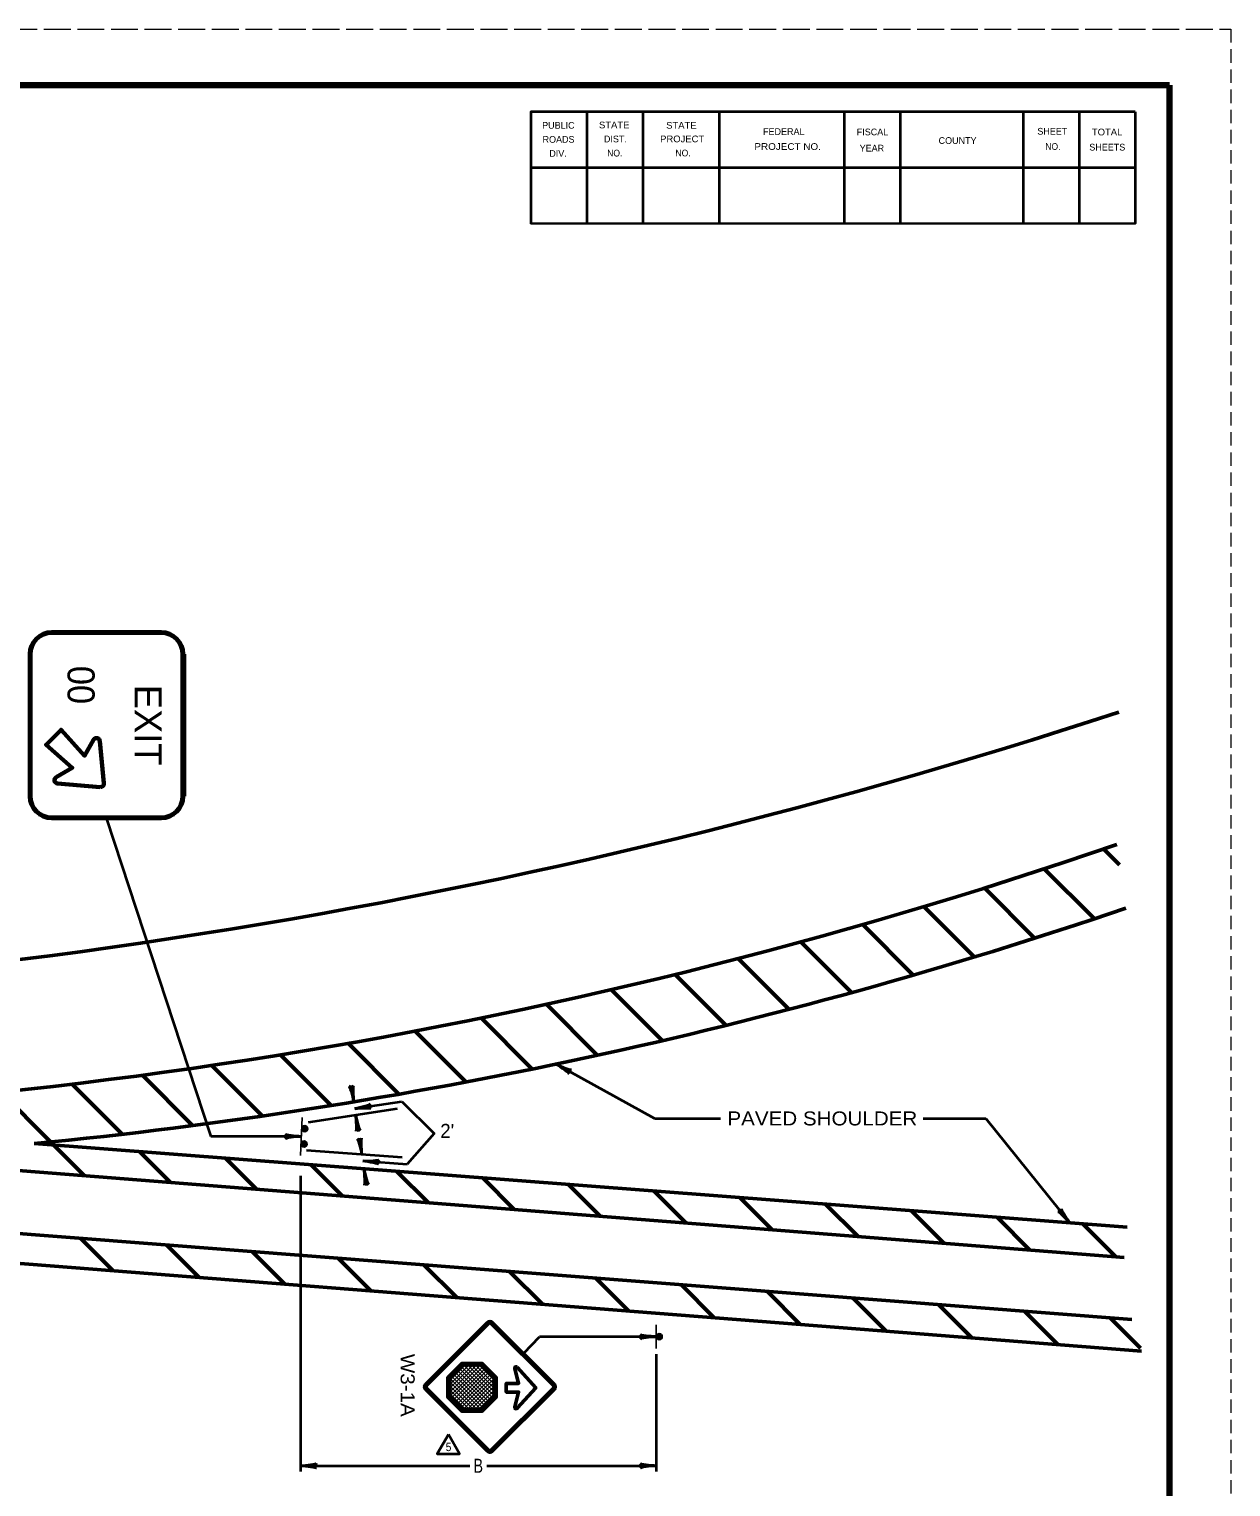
# Model space of a CAD drawing. Extents: x -281 to 399, y -258 to 182.
# Drawn here: x 184.7 to 399.4, y -78.8 to 181.6 of the extents above; entities that cross this region are included whole.
import ezdxf
from ezdxf.enums import TextEntityAlignment as Align

# ---------------------------------------------------------------- set-up
doc = ezdxf.new("R2010")
doc.units = 0
doc.header["$LTSCALE"] = 0.8
doc.linetypes.add('LONG_DASHED', pattern=[7.5, 6, -1.5])
doc.linetypes.add('MEDIUM_DASHED', pattern=[4.5, 3, -1.5])
for name, color, linetype, lineweight in [('1', 7, 'Continuous', 53), ('4', 7, 'Continuous', 25), ('61', 7, 'Continuous', 35)]:
    doc.layers.add(name, color=color, linetype=linetype, lineweight=lineweight)
doc.layers.add('2', color=7, linetype='Continuous')

msp = doc.modelspace()

# ---------------------------------------------------------------- hatches: boundary and pattern name
at = {"layer": '4'}
for points in [[(234.0025, -14.3221, 1), (233.9497, -15.4142, 1)], [(233.8666, -17.0612, 1), (233.8138, -18.1532, 1)], [(297.2901, -52.5626, 1), (297.2901, -51.4692, 1)]]:
    msp.add_hatch(color=256, dxfattribs=at).paths.add_polyline_path(points)

# ---------------------------------------------------------------- linework, layer by layer
at = {"layer": '1', "linetype": 'MEDIUM_DASHED', "lineweight": 13}
msp.add_line((399.3899, 181.553), (399.3699, -258.467), dxfattribs=at)
at = {"layer": '1', "lineweight": 13}
for p, q in [((188.816, 73.9491), (208.3032, 73.9491)), ((208.3032, 40.4701), (188.816, 40.4701)), ((255.3848, -60.5826), (266.6443, -49.3231)), ((267.4488, -49.3231), (278.7084, -60.5826)), ((266.6443, -72.6466), (255.3848, -61.3872)), ((278.7084, -61.3872), (267.4488, -72.6466))]:
    msp.add_line(p, q, dxfattribs=at)
at = {"layer": '1', "lineweight": 70}
for p, q in [((188.816, 73.7737), (208.3032, 73.7737)), ((184.9185, 44.5429), (184.9185, 69.8762)), ((212.2006, 69.8762), (212.2006, 44.5429)), ((212.3758, 69.8762), (212.3758, 44.5429)), ((208.3032, 40.6455), (188.816, 40.6455)), ((255.6529, -60.616), (266.678, -49.5908)), ((267.4151, -49.5908), (278.4406, -60.616)), ((266.678, -72.3786), (255.6529, -61.3534)), ((278.4406, -61.3534), (267.4151, -72.3786))]:
    msp.add_line(p, q, dxfattribs=at)
at = {"layer": '1', "lineweight": 60}
for p, q in [((198.0905, 46.8322), (197.3739, 54.3833)), ((189.8228, 46.8046), (197.429, 46.1709))]:
    msp.add_line(p, q, dxfattribs=at)
at = {"layer": '1', "lineweight": 35}
for p, q in [((198.5596, 40.4701), (217.1863, -16.2451)), ((296.448, -13.0323), (278.8727, -3.3218)), ((242.2686, -7.1048), (242.7253, -10.0699)), ((242.9123, -11.2834), (251.3292, -9.9868)), ((234.6656, -13.6853), (250.5111, -11.2443)), ((243.0825, -12.3887), (243.5392, -15.3537)), ((296.448, -13.0323), (308.2117, -13.0323)), ((344.4182, -13.0323), (355.6099, -13.0323)), ((355.6099, -13.0323), (370.6327, -31.6842)), ((233.3559, -16.2451), (217.1863, -16.2451)), ((243.712, -16.4758), (244.1688, -19.4409)), ((234.2569, -18.7163), (251.3497, -19.9658)), ((244.3504, -20.6193), (252.2623, -21.1977)), ((233.1867, -23.2798), (233.1867, -76.0738)), ((244.5684, -22.0352), (245.0251, -25.0001)), ((273.0787, -54.9528), (275.8959, -52.0159)), ((296.7568, -52.0159), (275.8959, -52.0159)), ((296.7568, -55.1492), (296.7568, -76.0738)), ((233.1867, -75.0738), (263.4717, -75.0738)), ((266.4717, -75.0738), (296.7568, -75.0738))]:
    msp.add_line(p, q, dxfattribs=at)
at = {"layer": '1'}
for p, q in [((379.5286, 32.2714), (376.659, 35.141)), ((374.995, 22.6629), (366.0127, 31.6452)), ((364.3436, 19.1722), (355.3664, 28.1493)), ((353.4922, 15.8814), (344.4977, 24.8759)), ((342.6407, 12.5907), (333.5824, 21.6491)), ((331.5705, 9.5187), (322.5365, 18.5528)), ((320.4375, 6.5097), (311.3434, 15.6037)), ((309.1587, 3.6464), (300.1063, 12.6988)), ((297.7339, 0.929), (288.6256, 10.0373)), ((286.2294, -1.7086), (277.1449, 7.3759)), ((262.7521, -6.5156), (253.6231, 2.6134)), ((274.5018, -4.1232), (265.4023, 4.9762)), ((250.7093, -8.6149), (241.6437, 0.4507)), ((238.6665, -10.7143), (229.5537, -1.6015)), ((226.3203, -12.5102), (217.3157, -3.5057)), ((201.294, -15.7682), (192.3803, -6.8545)), ((213.9486, -14.2806), (204.9017, -5.2338)), ((188.5777, -17.1941), (179.6273, -8.2436)), ((64.0117, -12.9926), (380.3567, -37.8742)), ((380.8884, -32.4693), (185.6334, -17.5242)), ((194.6516, -23.2678), (189.1793, -17.7957)), ((210.001, -24.4752), (204.4937, -18.9678)), ((225.3504, -25.6824), (219.808, -20.14)), ((240.6998, -26.8897), (235.1222, -21.3122)), ((256.0492, -28.097), (250.4366, -22.4843)), ((271.3987, -29.3043), (265.7509, -23.6565)), ((286.7481, -30.5116), (281.0652, -24.8287)), ((302.0975, -31.7189), (296.3795, -26.0008)), ((317.4469, -32.9262), (311.6938, -27.173)), ((332.7963, -34.1334), (327.0081, -28.3452)), ((348.1457, -35.3407), (342.3224, -29.5173)), ((363.4952, -36.548), (357.6368, -30.6896)), ((378.8447, -37.7553), (372.951, -31.8618)), ((199.7399, -40.2283), (193.9436, -34.432)), ((215.0813, -41.4277), (209.2687, -35.615)), ((230.4227, -42.6269), (224.5939, -36.7981)), ((245.7643, -43.8263), (239.919, -37.9811)), ((261.1057, -45.0256), (255.2442, -39.1641)), ((276.4471, -46.2249), (270.5693, -40.3471)), ((291.7886, -47.4242), (285.8945, -41.5301)), ((307.13, -48.6235), (301.2197, -42.7132)), ((322.4715, -49.8228), (316.5448, -43.8962)), ((337.8129, -51.0222), (331.8699, -45.0792)), ((353.1543, -52.2214), (347.1951, -46.2622)), ((368.4958, -53.4207), (362.5202, -47.4452)), ((383.2576, -54.0403), (377.8454, -48.6283)), ((271.4887, -57.6933), (272.1795, -60.3649))]:
    msp.add_line(p, q, dxfattribs=at)
at = {"layer": '1', "lineweight": 25}
for p, q in [((233.5251, -12.8492), (233.1867, -19.6409)), ((259.744, -59.9841), (262.7772, -56.9508)), ((259.744, -60.6731), (263.466, -56.9508)), ((259.744, -61.3619), (264.1548, -56.9508)), ((259.744, -62.0509), (264.844, -56.9508)), ((259.744, -62.7399), (265.5328, -56.9508)), ((267.6381, -63.0611), (261.8367, -57.2592)), ((267.9492, -62.6829), (262.2171, -56.9508)), ((267.9492, -61.9941), (262.906, -56.9508)), ((267.9492, -61.3052), (263.5952, -56.9508)), ((267.9492, -60.6159), (264.2842, -56.9508)), ((267.9492, -59.9271), (264.973, -56.9508)), ((265.5737, -65.1303), (259.7699, -59.3261)), ((260.0832, -63.0892), (265.8851, -57.2881)), ((265.9178, -64.7854), (260.1142, -58.9819)), ((260.4274, -63.4343), (266.2293, -57.6322)), ((266.262, -64.4404), (260.4585, -58.6375)), ((260.7716, -63.7792), (266.574, -57.9767)), ((266.6059, -64.0957), (260.8032, -58.2927)), ((261.1157, -64.1241), (266.9185, -58.3215)), ((266.9499, -63.7507), (261.1477, -57.9484)), ((261.4597, -64.4692), (267.2628, -58.6657)), ((267.294, -63.4059), (261.492, -57.6038)), ((261.8036, -64.814), (267.6075, -59.0104)), ((262.1506, -65.1561), (267.9492, -59.3573)), ((264.9104, -65.1561), (259.744, -59.9897)), ((264.2214, -65.1561), (259.744, -60.6786)), ((263.5324, -65.1561), (259.744, -61.3676)), ((262.8437, -65.1561), (259.744, -62.0565)), ((262.8396, -65.1561), (267.9492, -60.0466)), ((263.5287, -65.1561), (267.9492, -60.7354)), ((264.2174, -65.1561), (267.9492, -61.4244)), ((264.9065, -65.1561), (267.9492, -62.1133)), ((262.1544, -65.1561), (259.744, -62.7454))]:
    msp.add_line(p, q, dxfattribs=at)
at = {"layer": '1', "lineweight": 60}
msp.add_lwpolyline([(196.2577, 54.6175), (194.6318, 51.7514), (190.4428, 56.4089), (187.7697, 53.7357), (192.4547, 49.6017), (189.5749, 47.9346)], dxfattribs=at)
at = {"layer": '1'}
for points in [[(-241.1311, -9.5059), (-85.5166, -12.8592), (381.7234, -48.9276)], [(383.4217, -54.5876), (-6.4749, -24.1076), (-241.3148, -19.9913)], [(269.9762, -60.3649), (272.1795, -60.3649), (271.4887, -57.6933)], [(271.9108, -57.4703), (275.2274, -61.1328), (271.9108, -64.8025)], [(271.9108, -64.8025), (275.2274, -61.1328), (271.9108, -57.4703)], [(271.4887, -64.5722), (272.1795, -61.9082), (269.9762, -61.9082), (269.9762, -60.3649)], [(272.1795, -60.3649), (269.9762, -60.3649), (269.9762, -61.9082), (272.1795, -61.9082), (271.4887, -64.5722)]]:
    msp.add_lwpolyline(points, dxfattribs=at)
at = {"layer": '1', "lineweight": 35}
msp.add_lwpolyline([(251.3292, -9.9868), (257.1044, -15.7097), (252.2623, -21.1977)], dxfattribs=at)
for points in [[(259.4561, -59.2312), (262.03, -56.663), (265.6633, -56.663), (268.2369, -59.2312), (268.2369, -62.8702), (265.6633, -65.444), (262.03, -65.444), (259.4561, -62.8702)], [(259.6272, -69.4922), (257.6272, -72.9563), (261.6272, -72.9563)]]:
    msp.add_lwpolyline(points, close=True, dxfattribs=at)
at = {"layer": '1', "lineweight": 70}
msp.add_lwpolyline([(259.744, -59.3522), (262.1452, -56.9508), (265.5481, -56.9508), (267.9492, -59.3522), (267.9492, -62.7493), (265.5481, -65.1561), (262.1452, -65.1561), (259.744, -62.7493)], close=True, dxfattribs=at)
at = {"layer": '1', "lineweight": 13}
for centre, radius, start, end in [((188.8159, 69.8763), 4.0728, 90, 180), ((208.3031, 69.8763), 4.0728, 0, 90), ((188.8159, 44.543), 4.0728, 180, 270), ((208.3031, 44.543), 4.0728, 270, 0), ((267.0466, -49.725), 0.5687, 45, 135), ((255.787, -60.9847), 0.5687, 135, 225), ((278.3063, -60.9847), 0.5687, 315, 45), ((267.0466, -72.2444), 0.5687, 225, 315)]:
    msp.add_arc(centre, radius, start, end, dxfattribs=at)
at = {"layer": '1', "lineweight": 70}
for centre, radius, start, end in [((188.8159, 69.8763), 3.8974, 90, 180), ((208.3031, 69.8763), 3.8974, 0, 90), ((188.8159, 44.543), 3.8974, 180, 270), ((208.3031, 44.543), 3.8974, 270, 0), ((267.0466, -49.9596), 0.5213, 45, 135), ((256.0215, -60.9847), 0.5213, 135, 225), ((278.0718, -60.9847), 0.5213, 315, 45), ((267.0466, -72.0098), 0.5213, 225, 315)]:
    msp.add_arc(centre, radius, start, end, dxfattribs=at)
at = {"layer": '1'}
for centre, radius, start, end in [((52.4616, 1053.2806), 1046.1173, 269.11133, 288.21006), ((85.7097, 886.1487), 899.403, 268.61761, 289.03246), ((102.6244, 840.5928), 862.1226, 275.52525, 288.81251), ((271.7277, -57.634), 0.2464, 42.58363, 194.30223), ((271.7277, -57.634), 0.2464, 42.58363, 194.30223), ((271.7277, -64.635), 0.2464, 165.69778, 317.41638), ((271.7277, -64.635), 0.2464, 165.69778, 317.41638)]:
    msp.add_arc(centre, radius, start, end, dxfattribs=at)
at = {"layer": '1', "lineweight": 60}
for centre, start, end in [((196.7752, 54.3191), 5.43005, 150.55122), ((189.8712, 47.4052), 120.11373, 265.25762), ((197.487, 46.7748), 265.25653, 5.40471)]:
    msp.add_arc(centre, 0.6041, start, end, dxfattribs=at)
at = {"layer": '1', "lineweight": 40}
for centre, major_axis, ratio, start_param, end_param in [((279.7512, -4.0489), (-1.4525, 1.0032), 0.07063, 3.14071475, 5.41810995), ((279.7512, -4.0489), (-1.4525, 1.0032), 0.07063, 3.14071475, 5.41810995), ((279.9615, -3.6077), (-1.6385, 0.7269), 0.122415, 0.89635335, 3.14159265), ((279.9615, -3.6077), (-1.6385, 0.7269), 0.122415, 0.89635335, 3.14159265), ((242.2861, -9.0335), (0.4262, -1.7411), 0.122415, 0.89635335, 3.14159265), ((242.7639, -8.9303), (0.0938, -1.7627), 0.07063, 3.14071475, 5.41810995), ((243.9487, -10.8442), (-1.7411, -0.4262), 0.122415, 0.89635335, 3.14159265), ((243.9487, -10.8442), (-1.7411, -0.4262), 0.122415, 0.89635335, 3.14159265), ((244.0519, -11.322), (-1.7627, -0.0938), 0.07063, 3.14071475, 5.41810995), ((244.0519, -11.322), (-1.7627, -0.0938), 0.07063, 3.14071475, 5.41810995), ((243.044, -13.5284), (-0.0938, 1.7627), 0.07063, 3.14071475, 5.41810995), ((243.5217, -13.4252), (-0.4262, 1.7411), 0.122415, 0.89635335, 3.14159265), ((232.2647, -16.5214), (1.7857, 0.1562), 0.122415, 0.89635335, 3.14159265), ((232.2354, -16.0335), (1.7565, -0.1757), 0.07063, 3.14071475, 5.41810995), ((243.7296, -18.4045), (0.4262, -1.7411), 0.122415, 0.89635335, 3.14159265), ((244.2073, -18.3013), (0.0939, -1.7627), 0.07063, 3.14071475, 5.41810995), ((245.4525, -20.9121), (-1.739, 0.3032), 0.07063, 3.14071475, 5.41810995), ((245.4589, -20.4233), (-1.7923, -0.0256), 0.122415, 0.89635335, 3.14159265), ((244.5299, -23.1748), (-0.0938, 1.7627), 0.07063, 3.14071475, 5.41810995), ((245.0076, -23.0716), (-0.4262, 1.7411), 0.122415, 0.89635335, 3.14159265), ((369.7331, -31.0077), (1.2417, -1.2928), 0.122415, 0.89635335, 3.14159265), ((370.0947, -30.6789), (0.965, -1.4781), 0.07063, 3.14071475, 5.41810995), ((295.6656, -52.2922), (1.7857, 0.1562), 0.122415, 0.89635335, 3.14159265), ((295.6362, -51.8043), (1.7565, -0.1757), 0.07063, 3.14071475, 5.41810995), ((234.3073, -75.2854), (-1.7565, 0.1757), 0.07063, 3.14071475, 5.41810995), ((234.3073, -75.2854), (-1.7565, 0.1757), 0.07063, 3.14071475, 5.41810995), ((234.2779, -74.7975), (-1.7857, -0.1562), 0.122415, 0.89635335, 3.14159265), ((234.2779, -74.7975), (-1.7857, -0.1562), 0.122415, 0.89635335, 3.14159265), ((295.6656, -75.3501), (1.7857, 0.1562), 0.122415, 0.89635335, 3.14159265), ((295.6362, -74.8622), (1.7565, -0.1757), 0.07063, 3.14071475, 5.41810995)]:
    msp.add_ellipse(centre, major_axis=major_axis, ratio=ratio, start_param=start_param, end_param=end_param, dxfattribs=at)
at = {"layer": '4'}
msp.add_line((296.7568, -49.8826), (296.7568, -54.1492), dxfattribs=at)
for centre in [(233.9761, -14.8682), (233.8402, -17.6072), (297.2901, -52.0159)]:
    msp.add_circle(centre, 0.5467, dxfattribs=at)
at = {"layer": '61', "linetype": 'LONG_DASHED', "lineweight": 13}
msp.add_line((-280.6301, 181.553), (399.3899, 181.553), dxfattribs=at)
at = {"layer": '61', "lineweight": 158}
msp.add_line((388.4099, 171.553), (388.4299, -248.487), dxfattribs=at)
at = {"layer": '61'}
for p, q in [((284.3299, 166.793), (284.3299, 146.793)), ((294.3299, 166.793), (294.3299, 146.793)), ((308.0099, 166.793), (308.0099, 146.793)), ((330.3299, 166.793), (330.3299, 146.793)), ((340.3299, 166.793), (340.3299, 146.793)), ((362.3099, 166.813), (362.3099, 146.813)), ((372.3099, 166.813), (372.3099, 146.813)), ((382.3299, 156.773), (274.3099, 156.793))]:
    msp.add_line(p, q, dxfattribs=at)
at = {"layer": '61', "lineweight": 158}
msp.add_lwpolyline([(388.4099, 171.553), (-250.6301, 171.553), (-250.6301, -248.467)], dxfattribs=at)
at = {"layer": '61'}
for points in [[(382.3099, 166.813), (274.3299, 166.793), (274.3299, 146.793)], [(382.3099, 166.813), (382.3099, 146.813), (274.3299, 146.793)]]:
    msp.add_lwpolyline(points, dxfattribs=at)

# ---------------------------------------------------------------- texts
at = {"layer": '1', "width": 0.95}
msp.add_text('00', height=4.84, rotation=270, dxfattribs=at).set_placement((191.5978, 64.4038), align=Align.CENTER)
at = {"layer": '1'}
msp.add_text('EXIT', height=4.84, rotation=270, dxfattribs=at).set_placement((203.593, 57.2296), align=Align.CENTER)
for s, width, p in [('PAVED SHOULDER', 1.1, (326.424, -14.2823)), ('B', 0.75, (264.9717, -76.3238))]:
    msp.add_text(s, height=2.5, dxfattribs=dict(at, width=width)).set_placement(p, align=Align.CENTER)
msp.add_text("2'", height=2.5, dxfattribs=at).set_placement((259.4234, -16.5018), align=Align.CENTER)
at = {"layer": '1', "width": 0.9}
msp.add_text('5', height=1.5, dxfattribs=at).set_placement((259.1505, -72.4555))
at = {"layer": '2', "width": 1.1}
msp.add_text('W3-1A', height=2.5, rotation=270, dxfattribs=at).set_placement((251.1031, -60.701), align=Align.CENTER)
at = {"layer": '61'}
for s, rotation, p in [('PUBLIC', 0.033, (276.3699, 163.773)), ('ROADS', 0.124, (276.4499, 161.253)), ('DIST.', 0.056, (287.4099, 161.333)), ('FEDERAL', 0.007, (315.8299, 162.653)), ('FISCAL', 359.942, (332.5699, 162.593)), ('COUNTY', 0.069, (347.1899, 161.053)), ('SHEET', 0.059, (364.8299, 162.713)), ('DIV.', 359.932, (277.6499, 158.753)), ('YEAR', 0.105, (333.0899, 159.693)), ('SHEETS', 359.959, (374.1099, 159.873))]:
    msp.add_text(s, height=1.201, rotation=rotation, dxfattribs=at).set_placement(p)
for s, rotation, width, p in [('STATE', 0.059, 1.05, (286.5299, 163.833)), ('STATE', 0.059, 1.05, (298.5299, 163.773)), ('PROJECT', 359.908, 1.05, (297.4499, 161.353)), ('TOTAL', 359.926, 1.05, (374.5699, 162.573)), ('NO.', 359.852, 0.95, (287.9899, 158.813)), ('NO.', 0.225, 0.95, (300.1899, 158.813)), ('PROJECT NO.', 359.922, 1.1, (314.2899, 159.993)), ('NO.', 359.852, 0.95, (366.2499, 159.993))]:
    msp.add_text(s, height=1.201, rotation=rotation, dxfattribs=dict(at, width=width)).set_placement(p)

doc.saveas('drawing.dxf')
